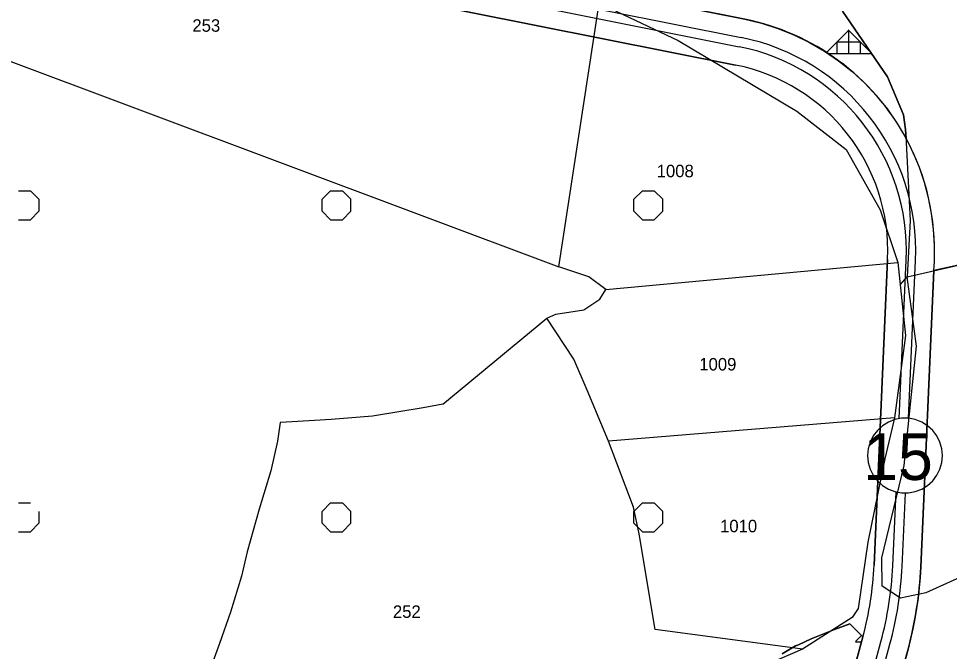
# Model space of a CAD drawing. Extents: x 410727 to 412947, y 4463506 to 4466382.
# Drawn here: x 411696.5 to 411994.9, y 4465344.3 to 4465547.1 of the extents above; entities that cross this region are included whole.
import ezdxf

# ---------------------------------------------------------------- set-up
doc = ezdxf.new("R2010")
doc.units = 0
for name, color, linetype in [('ADAKENARI', 7, 'Continuous'), ('KALDIRIM', 7, 'Continuous'), ('KD_DAIRE', 7, 'Continuous'), ('KD_YGEN', 7, 'Continuous'), ('KDS_PARSEL_NO', 7, 'Continuous'), ('KDS_PL', 7, 'Continuous'), ('PL_AYA_ORMAN', 7, 'Continuous'), ('PL_KA_TARIM_DIGER', 7, 'Continuous'), ('TR_ORMAN', 7, 'Continuous'), ('TR_TARIMALANI', 7, 'Continuous')]:
    doc.layers.add(name, color=color, linetype=linetype)

msp = doc.modelspace()

# ---------------------------------------------------------------- linework, layer by layer
at = {"layer": 'ADAKENARI'}
for p, q in [((411929.27, 4465546.92), (411860.27, 4465560.72)), ((411819.96, 4465553.48), (411926.33, 4465532.21)), ((411819.96, 4465553.48), (411926.33, 4465532.21)), ((411960.61, 4465549.47), (411975.01, 4465528.47)), ((411975.01, 4465528.47), (411980.16, 4465516.22)), ((411980.16, 4465516.22), (411980.88, 4465511.59)), ((411980.88, 4465511.59), (411981.02, 4465508.72)), ((411975.1, 4465469.95), (411970.74, 4465371.95)), ((411975.1, 4465469.95), (411970.74, 4465371.95)), ((411989.95, 4465466.32), (411990.08, 4465469.28)), ((411989.95, 4465466.32), (411998.67, 4465468.29)), ((411985.73, 4465371.28), (411989.95, 4465466.32)), ((411950.62, 4465348.29), (411958.1, 4465351.35)), ((411958.1, 4465351.35), (411962.94, 4465353.14)), ((411962.94, 4465353.14), (411967.17, 4465348.98)), ((411946.51, 4465346.39), (411950.62, 4465348.29)), ((411967.17, 4465348.98), (411948.9, 4465281.54)), ((411941.33, 4465343.58), (411945.51, 4465346.13)), ((411945.51, 4465346.13), (411946.51, 4465346.39)), ((411963.38, 4465277.62), (411981.64, 4465345.06))]:
    msp.add_line(p, q, dxfattribs=at)
for centre, radius, start, end in [((411914.42, 4465472.65), 75.74, 28.4407, 78.6901), ((411914.42, 4465472.65), 75.74, 28.4407, 78.6901), ((411914.42, 4465472.65), 60.74, 357.4552, 78.6901), ((411914.42, 4465472.65), 60.74, 357.4552, 78.6901), ((411914.42, 4465472.65), 60.74, 357.4552, 78.6901), ((411914.42, 4465472.65), 60.74, 357.4552, 78.6901), ((411914.42, 4465472.65), 75.74, 357.4552, 28.4407), ((411914.42, 4465472.65), 75.74, 357.4552, 28.4407), ((411865, 4465376.65), 105.85, 344.8459, 357.4552), ((411865, 4465376.65), 105.85, 344.8459, 357.4552), ((411865, 4465376.65), 105.85, 344.8459, 357.4552), ((411865, 4465376.65), 105.85, 344.8459, 357.4552), ((411865, 4465376.65), 120.85, 344.8459, 357.4552), ((411865, 4465376.65), 120.85, 344.8459, 357.4552)]:
    msp.add_arc(centre, radius, start, end, dxfattribs=at)
at = {"layer": 'KALDIRIM'}
for p, q in [((411821.73, 4465562.31), (411928.09, 4465541.03)), ((411821.14, 4465559.37), (411927.51, 4465538.09)), ((411978.84, 4465418.92), (411981.09, 4465469.68)), ((411981.84, 4465419.01), (411984.09, 4465469.55)), ((411976.74, 4465371.68), (411977.79, 4465395.42)), ((411979.73, 4465371.55), (411980.78, 4465395.07)), ((411954.69, 4465279.97), (411972.96, 4465347.41)), ((411957.59, 4465279.19), (411975.85, 4465346.63))]:
    msp.add_line(p, q, dxfattribs=at)
for centre, radius, start, end in [((411914.42, 4465472.65), 69.74, 357.4552, 78.6901), ((411914.42, 4465472.65), 69.74, 357.4552, 78.6901), ((411914.42, 4465472.65), 66.74, 357.4552, 78.6901), ((411914.42, 4465472.65), 66.74, 357.4552, 78.6901), ((411865, 4465376.65), 111.85, 344.8459, 357.4552), ((411865, 4465376.65), 111.85, 344.8459, 357.4552), ((411865, 4465376.65), 114.85, 344.8459, 357.4552), ((411865, 4465376.65), 114.85, 344.8459, 357.4552)]:
    msp.add_arc(centre, radius, start, end, dxfattribs=at)
at = {"layer": 'KD_DAIRE'}
for p, q in [((411975.35, 4465417.81), (411973.46, 4465416.64)), ((411977.41, 4465418.61), (411975.35, 4465417.81)), ((411979.59, 4465419.02), (411977.41, 4465418.61)), ((411981.8, 4465419.02), (411979.59, 4465419.02)), ((411983.98, 4465418.61), (411981.8, 4465419.02)), ((411986.04, 4465417.81), (411983.98, 4465418.61)), ((411987.93, 4465416.64), (411986.04, 4465417.81)), ((411971.83, 4465415.15), (411970.49, 4465413.38)), ((411973.46, 4465416.64), (411971.83, 4465415.15)), ((411989.56, 4465415.15), (411987.93, 4465416.64)), ((411990.9, 4465413.38), (411989.56, 4465415.15)), ((411969.51, 4465411.4), (411968.9, 4465409.27)), ((411970.49, 4465413.38), (411969.51, 4465411.4)), ((411991.89, 4465411.4), (411990.9, 4465413.38)), ((411992.49, 4465409.27), (411991.89, 4465411.4)), ((411968.9, 4465409.27), (411968.7, 4465407.07)), ((411992.7, 4465407.07), (411992.49, 4465409.27)), ((411968.7, 4465407.07), (411968.9, 4465404.86)), ((411992.49, 4465404.86), (411992.7, 4465407.07)), ((411992.7, 4465407.07), (411992.7, 4465407.07)), ((411968.9, 4465404.86), (411969.51, 4465402.73)), ((411969.51, 4465402.73), (411970.49, 4465400.75)), ((411990.9, 4465400.75), (411991.89, 4465402.73)), ((411991.89, 4465402.73), (411992.49, 4465404.86)), ((411970.49, 4465400.75), (411971.83, 4465398.98)), ((411971.83, 4465398.98), (411973.46, 4465397.49)), ((411987.93, 4465397.49), (411989.56, 4465398.98)), ((411989.56, 4465398.98), (411990.9, 4465400.75)), ((411973.46, 4465397.49), (411975.35, 4465396.32)), ((411975.35, 4465396.32), (411977.41, 4465395.52)), ((411983.98, 4465395.52), (411986.04, 4465396.32)), ((411986.04, 4465396.32), (411987.93, 4465397.49)), ((411977.41, 4465395.52), (411979.59, 4465395.12)), ((411979.59, 4465395.12), (411981.8, 4465395.12)), ((411981.8, 4465395.12), (411983.98, 4465395.52))]:
    msp.add_line(p, q, dxfattribs=at)
at = {"layer": 'KDS_PL'}
for p, q in [((411869.65, 4465467.6), (411882.34, 4465549.88)), ((411886.43, 4465550.24), (411907.97, 4465540.04)), ((411960.61, 4465549.47), (411975.01, 4465528.47)), ((411666.06, 4465543.82), (411869.65, 4465467.6)), ((411907.97, 4465540.04), (411945.94, 4465517.42)), ((411975.01, 4465528.47), (411980.16, 4465516.22)), ((411945.94, 4465517.42), (411961.83, 4465505.2)), ((411980.16, 4465516.22), (411980.88, 4465511.59)), ((411980.88, 4465511.59), (411982.32, 4465482.35)), ((411961.83, 4465505.2), (411972.76, 4465485.77)), ((411972.76, 4465485.77), (411978.41, 4465468.94)), ((411982.32, 4465482.35), (411981.39, 4465464.38)), ((411884.75, 4465460.29), (411978.41, 4465468.94)), ((411978.41, 4465468.94), (411980.79, 4465445.55)), ((411981.39, 4465464.38), (411998.67, 4465468.29)), ((411879.31, 4465464.31), (411869.65, 4465467.6)), ((411884.75, 4465460.29), (411879.31, 4465464.31)), ((411979.14, 4465461.79), (411981.39, 4465464.38)), ((411984.36, 4465442.08), (411981.39, 4465464.38)), ((411882.81, 4465457.19), (411884.75, 4465460.29)), ((411877.66, 4465453.79), (411882.81, 4465457.19)), ((411868.74, 4465452.36), (411877.66, 4465453.79)), ((411832.53, 4465423.49), (411865.86, 4465451.15)), ((411865.86, 4465451.15), (411868.74, 4465452.36)), ((411874.51, 4465437.96), (411865.86, 4465451.15)), ((411980.79, 4465445.55), (411977.26, 4465419.16)), ((411980.44, 4465403.86), (411984.36, 4465442.08)), ((411878.78, 4465428.03), (411874.51, 4465437.96)), ((411885.61, 4465411.63), (411878.78, 4465428.03)), ((411832.53, 4465423.49), (411826.17, 4465422.35)), ((411826.17, 4465422.35), (411809.93, 4465419.74)), ((411780.29, 4465417.69), (411779.49, 4465411.66)), ((411784.15, 4465417.92), (411780.29, 4465417.69)), ((411796.64, 4465418.6), (411784.15, 4465417.92)), ((411809.93, 4465419.74), (411796.64, 4465418.6)), ((411977.26, 4465419.16), (411885.61, 4465411.63)), ((411977.26, 4465419.16), (411974.25, 4465406)), ((411779.49, 4465411.66), (411777.33, 4465402.21)), ((411893.66, 4465390.57), (411885.61, 4465411.63)), ((411974.25, 4465406), (411968.8, 4465379.32)), ((411777.33, 4465402.21), (411773.59, 4465389.92)), ((411973.21, 4465374.32), (411980.44, 4465403.86)), ((411895.41, 4465381.95), (411893.66, 4465390.57)), ((411773.59, 4465389.92), (411769.72, 4465376.26)), ((411900.56, 4465351.35), (411895.41, 4465381.95)), ((411968.8, 4465379.32), (411965.69, 4465358.09)), ((412022.68, 4465379.08), (411987.36, 4465363.07)), ((411769.72, 4465376.26), (411767.91, 4465368.41)), ((411973.31, 4465365.24), (411973.21, 4465374.32)), ((411767.91, 4465368.41), (411764.39, 4465356.92)), ((411979.2, 4465361.41), (411973.31, 4465365.24)), ((411987.36, 4465363.07), (411979.2, 4465361.41)), ((411965.69, 4465358.09), (411963.78, 4465355.2)), ((411764.39, 4465356.92), (411760.86, 4465346.79)), ((411963.78, 4465355.2), (411947.8, 4465345.07)), ((411947.8, 4465345.07), (411900.56, 4465351.35)), ((411760.86, 4465346.79), (411757.91, 4465338.6)), ((411947.8, 4465345.07), (411925.88, 4465335.57))]:
    msp.add_line(p, q, dxfattribs=at)
at = {"layer": 'PL_AYA_ORMAN'}
for points in [[(411860.27, 4465560.72), (411929.27, 4465546.92), (411934.65, 4465545.63), (411939.93, 4465543.96), (411945.07, 4465541.91), (411950.04, 4465539.49), (411954.83, 4465536.71), (411959.4, 4465533.58), (411963.73, 4465530.14), (411967.8, 4465526.38), (411971.58, 4465522.34), (411975.05, 4465518.03), (411978.2, 4465513.49), (411981.02, 4465508.72), (411980.88, 4465511.59), (411980.16, 4465516.22), (411975.01, 4465528.47), (411960.61, 4465549.47)], [(411998.67, 4465468.29), (411989.95, 4465466.32), (411985.73, 4465371.28), (411985.53, 4465367.96), (411985.25, 4465364.65), (411984.87, 4465361.35), (411984.41, 4465358.06), (411983.85, 4465354.78), (411983.2, 4465351.52), (411982.47, 4465348.28), (411981.64, 4465345.06), (411963.38, 4465277.62)], [(411948.9, 4465281.54), (411967.17, 4465348.98), (411962.94, 4465353.14), (411958.1, 4465351.35), (411950.62, 4465348.29), (411946.51, 4465346.39), (411945.51, 4465346.13), (411941.33, 4465343.58)]]:
    msp.add_lwpolyline(points, dxfattribs=at)
at = {"layer": 'PL_KA_TARIM_DIGER'}
for points in [[(411926.33, 4465532.21), (411819.96, 4465553.48)], [(411998.67, 4465468.29), (411989.95, 4465466.32), (411990.08, 4465469.28), (411990.14, 4465474.4), (411989.85, 4465479.51), (411989.21, 4465484.59), (411988.23, 4465489.62), (411986.92, 4465494.57), (411985.27, 4465499.41), (411983.3, 4465504.14), (411981.02, 4465508.72), (411980.88, 4465511.59), (411980.16, 4465516.22), (411975.01, 4465528.47), (411960.61, 4465549.47)], [(411970.74, 4465371.95), (411975.1, 4465469.95)], [(411941.33, 4465343.58), (411945.51, 4465346.13), (411946.51, 4465346.39), (411950.62, 4465348.29), (411958.1, 4465351.35), (411962.94, 4465353.14), (411967.17, 4465348.98)]]:
    msp.add_lwpolyline(points, dxfattribs=at)
for centre, radius, start, end in [((411914.42, 4465472.65), 60.74, 357.4552, 78.6901), ((411865, 4465376.65), 105.85, 344.8459, 357.4552)]:
    msp.add_arc(centre, radius, start, end, dxfattribs=at)
at = {"layer": 'TR_ORMAN'}
for p, q in [((411955.52, 4465536.23), (411962.66, 4465543.38)), ((411955.52, 4465536.23), (411962.66, 4465543.38)), ((411969.64, 4465536.31), (411962.49, 4465543.46)), ((411969.64, 4465536.31), (411962.49, 4465543.46)), ((411962.67, 4465535.86), (411962.67, 4465543.36)), ((411962.67, 4465535.86), (411962.67, 4465543.36)), ((411958.92, 4465535.86), (411958.92, 4465539.61)), ((411958.92, 4465539.61), (411966.42, 4465539.61)), ((411958.92, 4465535.86), (411958.92, 4465539.61)), ((411958.92, 4465539.61), (411966.42, 4465539.61)), ((411966.42, 4465535.86), (411966.42, 4465539.61)), ((411966.42, 4465535.86), (411966.42, 4465539.61)), ((411956.07, 4465535.86), (411969.94, 4465535.86)), ((411956.07, 4465535.86), (411969.94, 4465535.86)), ((411964.79, 4465347.48), (411966.72, 4465349.42)), ((411964.79, 4465347.48), (411966.72, 4465349.42)), ((411964.79, 4465347.48), (411966.72, 4465349.42)), ((411964.79, 4465347.48), (411966.72, 4465349.42)), ((411964.81, 4465347.41), (411966.74, 4465347.41)), ((411964.81, 4465347.41), (411966.74, 4465347.41)), ((411964.81, 4465347.41), (411966.74, 4465347.41)), ((411964.81, 4465347.41), (411966.74, 4465347.41))]:
    msp.add_line(p, q, dxfattribs=at)
at = {"layer": 'TR_TARIMALANI'}
for p, q in [((411696.46, 4465491.9), (411700.29, 4465491.9)), ((411696.46, 4465491.9), (411700.29, 4465491.9)), ((411702.99, 4465489.19), (411700.28, 4465491.9)), ((411702.99, 4465489.19), (411700.28, 4465491.9)), ((411793.74, 4465489.19), (411796.45, 4465491.9)), ((411793.74, 4465489.19), (411796.45, 4465491.9)), ((411796.46, 4465491.9), (411800.29, 4465491.9)), ((411796.46, 4465491.9), (411800.29, 4465491.9)), ((411802.99, 4465489.19), (411800.28, 4465491.9)), ((411802.99, 4465489.19), (411800.28, 4465491.9)), ((411893.74, 4465489.19), (411896.45, 4465491.9)), ((411893.74, 4465489.19), (411896.45, 4465491.9)), ((411896.46, 4465491.9), (411900.29, 4465491.9)), ((411896.46, 4465491.9), (411900.29, 4465491.9)), ((411902.99, 4465489.19), (411900.28, 4465491.9)), ((411902.99, 4465489.19), (411900.28, 4465491.9)), ((411703, 4465485.36), (411703, 4465489.19)), ((411703, 4465485.36), (411703, 4465489.19)), ((411793.75, 4465485.36), (411793.75, 4465489.19)), ((411793.75, 4465485.36), (411793.75, 4465489.19)), ((411803, 4465485.36), (411803, 4465489.19)), ((411803, 4465485.36), (411803, 4465489.19)), ((411893.75, 4465485.36), (411893.75, 4465489.19)), ((411893.75, 4465485.36), (411893.75, 4465489.19)), ((411903, 4465485.36), (411903, 4465489.19)), ((411903, 4465485.36), (411903, 4465489.19)), ((411696.46, 4465482.65), (411700.29, 4465482.65)), ((411696.46, 4465482.65), (411700.29, 4465482.65)), ((411700.28, 4465482.65), (411702.99, 4465485.36)), ((411700.28, 4465482.65), (411702.99, 4465485.36)), ((411796.45, 4465482.65), (411793.74, 4465485.36)), ((411796.45, 4465482.65), (411793.74, 4465485.36)), ((411796.46, 4465482.65), (411800.29, 4465482.65)), ((411796.46, 4465482.65), (411800.29, 4465482.65)), ((411800.28, 4465482.65), (411802.99, 4465485.36)), ((411800.28, 4465482.65), (411802.99, 4465485.36)), ((411896.45, 4465482.65), (411893.74, 4465485.36)), ((411896.45, 4465482.65), (411893.74, 4465485.36)), ((411896.46, 4465482.65), (411900.29, 4465482.65)), ((411896.46, 4465482.65), (411900.29, 4465482.65)), ((411900.28, 4465482.65), (411902.99, 4465485.36)), ((411900.28, 4465482.65), (411902.99, 4465485.36)), ((411696.46, 4465391.9), (411700.29, 4465391.9)), ((411696.46, 4465391.9), (411700.29, 4465391.9)), ((411793.74, 4465389.19), (411796.45, 4465391.9)), ((411793.74, 4465389.19), (411796.45, 4465391.9)), ((411796.46, 4465391.9), (411800.29, 4465391.9)), ((411796.46, 4465391.9), (411800.29, 4465391.9)), ((411802.99, 4465389.19), (411800.28, 4465391.9)), ((411802.99, 4465389.19), (411800.28, 4465391.9)), ((411893.74, 4465389.19), (411896.45, 4465391.9)), ((411893.74, 4465389.19), (411896.45, 4465391.9)), ((411896.46, 4465391.9), (411900.29, 4465391.9)), ((411896.46, 4465391.9), (411900.29, 4465391.9)), ((411902.99, 4465389.19), (411900.28, 4465391.9)), ((411902.99, 4465389.19), (411900.28, 4465391.9)), ((411703, 4465385.36), (411703, 4465389.19)), ((411703, 4465385.36), (411703, 4465389.19)), ((411793.75, 4465385.36), (411793.75, 4465389.19)), ((411793.75, 4465385.36), (411793.75, 4465389.19)), ((411803, 4465385.36), (411803, 4465389.19)), ((411803, 4465385.36), (411803, 4465389.19)), ((411893.75, 4465385.36), (411893.75, 4465389.19)), ((411893.75, 4465385.36), (411893.75, 4465389.19)), ((411903, 4465385.36), (411903, 4465389.19)), ((411903, 4465385.36), (411903, 4465389.19)), ((411700.28, 4465382.65), (411702.99, 4465385.36)), ((411700.28, 4465382.65), (411702.99, 4465385.36)), ((411796.45, 4465382.65), (411793.74, 4465385.36)), ((411796.45, 4465382.65), (411793.74, 4465385.36)), ((411800.28, 4465382.65), (411802.99, 4465385.36)), ((411800.28, 4465382.65), (411802.99, 4465385.36)), ((411896.45, 4465382.65), (411893.74, 4465385.36)), ((411896.45, 4465382.65), (411893.74, 4465385.36)), ((411900.28, 4465382.65), (411902.99, 4465385.36)), ((411900.28, 4465382.65), (411902.99, 4465385.36)), ((411696.46, 4465382.65), (411700.29, 4465382.65)), ((411696.46, 4465382.65), (411700.29, 4465382.65)), ((411796.46, 4465382.65), (411800.29, 4465382.65)), ((411796.46, 4465382.65), (411800.29, 4465382.65)), ((411896.46, 4465382.65), (411900.29, 4465382.65)), ((411896.46, 4465382.65), (411900.29, 4465382.65))]:
    msp.add_line(p, q, dxfattribs=at)

# ---------------------------------------------------------------- texts
at = {"layer": 'KD_YGEN'}
msp.add_text('15', height=15, dxfattribs=at).set_placement((411967.28, 4465399.24))
at = {"layer": 'KDS_PARSEL_NO'}
for s, p in [('253', (411752.17, 4465542.88)), ('1008', (411901.05, 4465496.26)), ('1009', (411914.71, 4465434.33)), ('1010', (411921.37, 4465382.48)), ('252', (411816.47, 4465355.06))]:
    msp.add_text(s, height=4, dxfattribs=at).set_placement(p)

doc.saveas('drawing.dxf')
